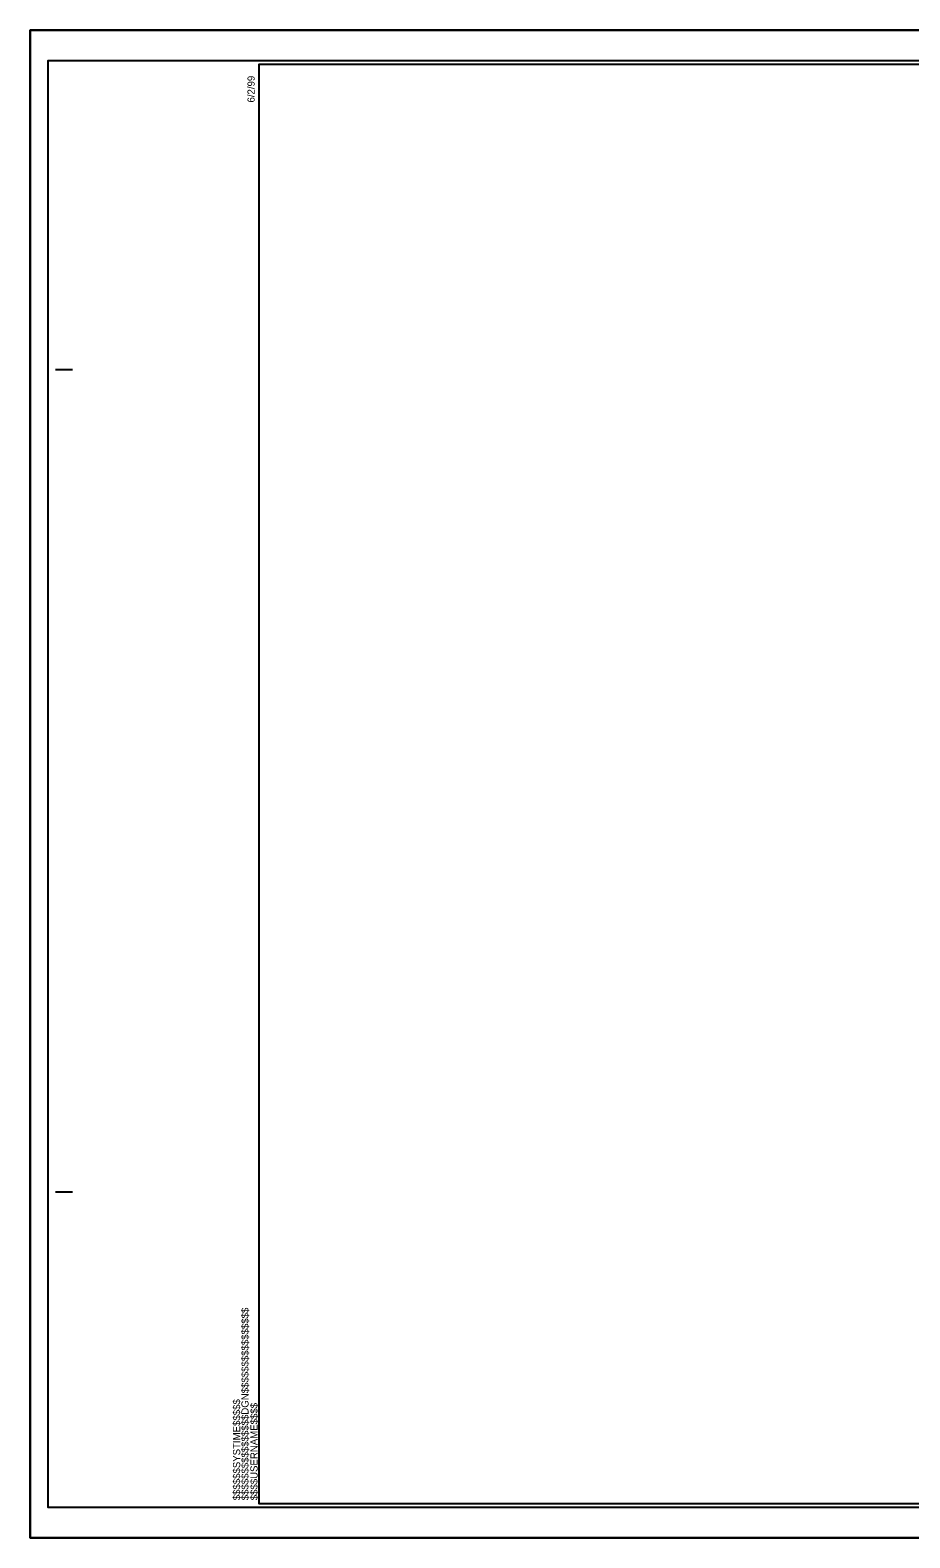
# Model space of a CAD drawing. Extents: x 1733676 to 1734289, y 540979 to 541226.
# Drawn here: x 1733676.5 to 1733745.8, y 540979.4 to 541098.2 of the extents above; entities that cross this region are included whole.
import ezdxf

# ---------------------------------------------------------------- set-up
doc = ezdxf.new("R2010")
doc.units = 0
for name, color, linetype in [('Prop Dimension', 7, 'Continuous'), ('Sheet Cutting Line CELL', 7, 'Continuous'), ('Sheet Plot Border Inside CELL', 7, 'Continuous'), ('Sheet Plot Border Outside CELL', 7, 'Continuous'), ('Sheet Typical CELL', 7, 'Continuous')]:
    doc.layers.add(name, color=color, linetype=linetype)

msp = doc.modelspace()

# ---------------------------------------------------------------- linework, layer by layer
at = {"layer": 'Prop Dimension'}
msp.add_lwpolyline([(1733676.47, 541098.22), (1733858.34, 541098.22), (1733858.34, 540979.42), (1733676.47, 540979.42)], close=True, dxfattribs=at)
msp.add_lwpolyline([(1733676.47, 541098.22), (1733858.34, 541098.22), (1733858.34, 540979.42), (1733676.47, 540979.42)], close=True, dxfattribs=at)
at = {"layer": 'Sheet Cutting Line CELL'}
for p, q in [((1733858.34, 541098.22), (1733676.47, 541098.22)), ((1733676.47, 541098.22), (1733676.47, 540979.42)), ((1733676.47, 540979.42), (1733858.34, 540979.42))]:
    msp.add_line(p, q, dxfattribs=at)
at = {"layer": 'Sheet Plot Border Inside CELL'}
msp.add_lwpolyline([(1733857.85, 541095.8), (1733677.87, 541095.8), (1733677.87, 540981.85), (1733857.85, 540981.85)], close=True, dxfattribs=at)
at = {"layer": 'Sheet Plot Border Outside CELL'}
msp.add_lwpolyline([(1733858.34, 541098.22), (1733676.47, 541098.22), (1733676.47, 540979.42), (1733858.34, 540979.42)], close=True, dxfattribs=at)
at = {"layer": 'Sheet Typical CELL'}
for p, q in [((1733678.46, 541071.49), (1733679.81, 541071.49)), ((1733678.46, 541006.69), (1733679.81, 541006.69)), ((1733694.5, 540982.12), (1733694.5, 540982.12)), ((1733694.5, 540982.12), (1733694.5, 540982.12)), ((1733694.5, 540982.12), (1733694.5, 540982.12)), ((1733694.5, 540982.12), (1733694.5, 540982.12)), ((1733694.5, 540982.12), (1733694.5, 540982.12)), ((1733694.5, 540982.12), (1733694.5, 540982.12))]:
    msp.add_line(p, q, dxfattribs=at)
msp.add_lwpolyline([(1733856.5, 541095.52), (1733694.5, 541095.52), (1733694.5, 540982.12), (1733856.5, 540982.12)], close=True, dxfattribs=at)
msp.add_lwpolyline([(1733698.55, 540982.12), (1733698.55, 540982.12)], dxfattribs=at)

# ---------------------------------------------------------------- texts
for s, p in [('6/2/99', (1733694.16, 541092.52)), ('$$$$$$$$$$$$$$$$DGN$$$$$$$$$$$$$$$$', (1733693.68, 540982.38)), ('$$$$$$SYSTIME$$$$$', (1733693.02, 540982.38)), ('$$$$USERNAME$$$$', (1733694.39, 540982.38))]:
    msp.add_text(s, height=0.567, rotation=90, dxfattribs=at).set_placement(p)

doc.saveas('drawing.dxf')
